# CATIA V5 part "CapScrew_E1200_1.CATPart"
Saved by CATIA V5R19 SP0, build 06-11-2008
Part number: CapScrew_E1200_1
Nomenclature: E 1200/4x30
Source: Unknown
Description: MEUSBURGER
Bounding box of the stored display mesh (mm): x -3.499 to 3.499, y -3.499 to 3.495, z 0 to 34
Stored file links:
  C:\Users\jsmid\Desktop\DP_Smidak_Forma LEGO\CapScrew_E1200_1.CATPart
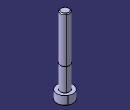
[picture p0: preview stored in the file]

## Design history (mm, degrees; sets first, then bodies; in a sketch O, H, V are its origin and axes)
Body1 (main body)
  Solid1 "PartBody": solid without history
